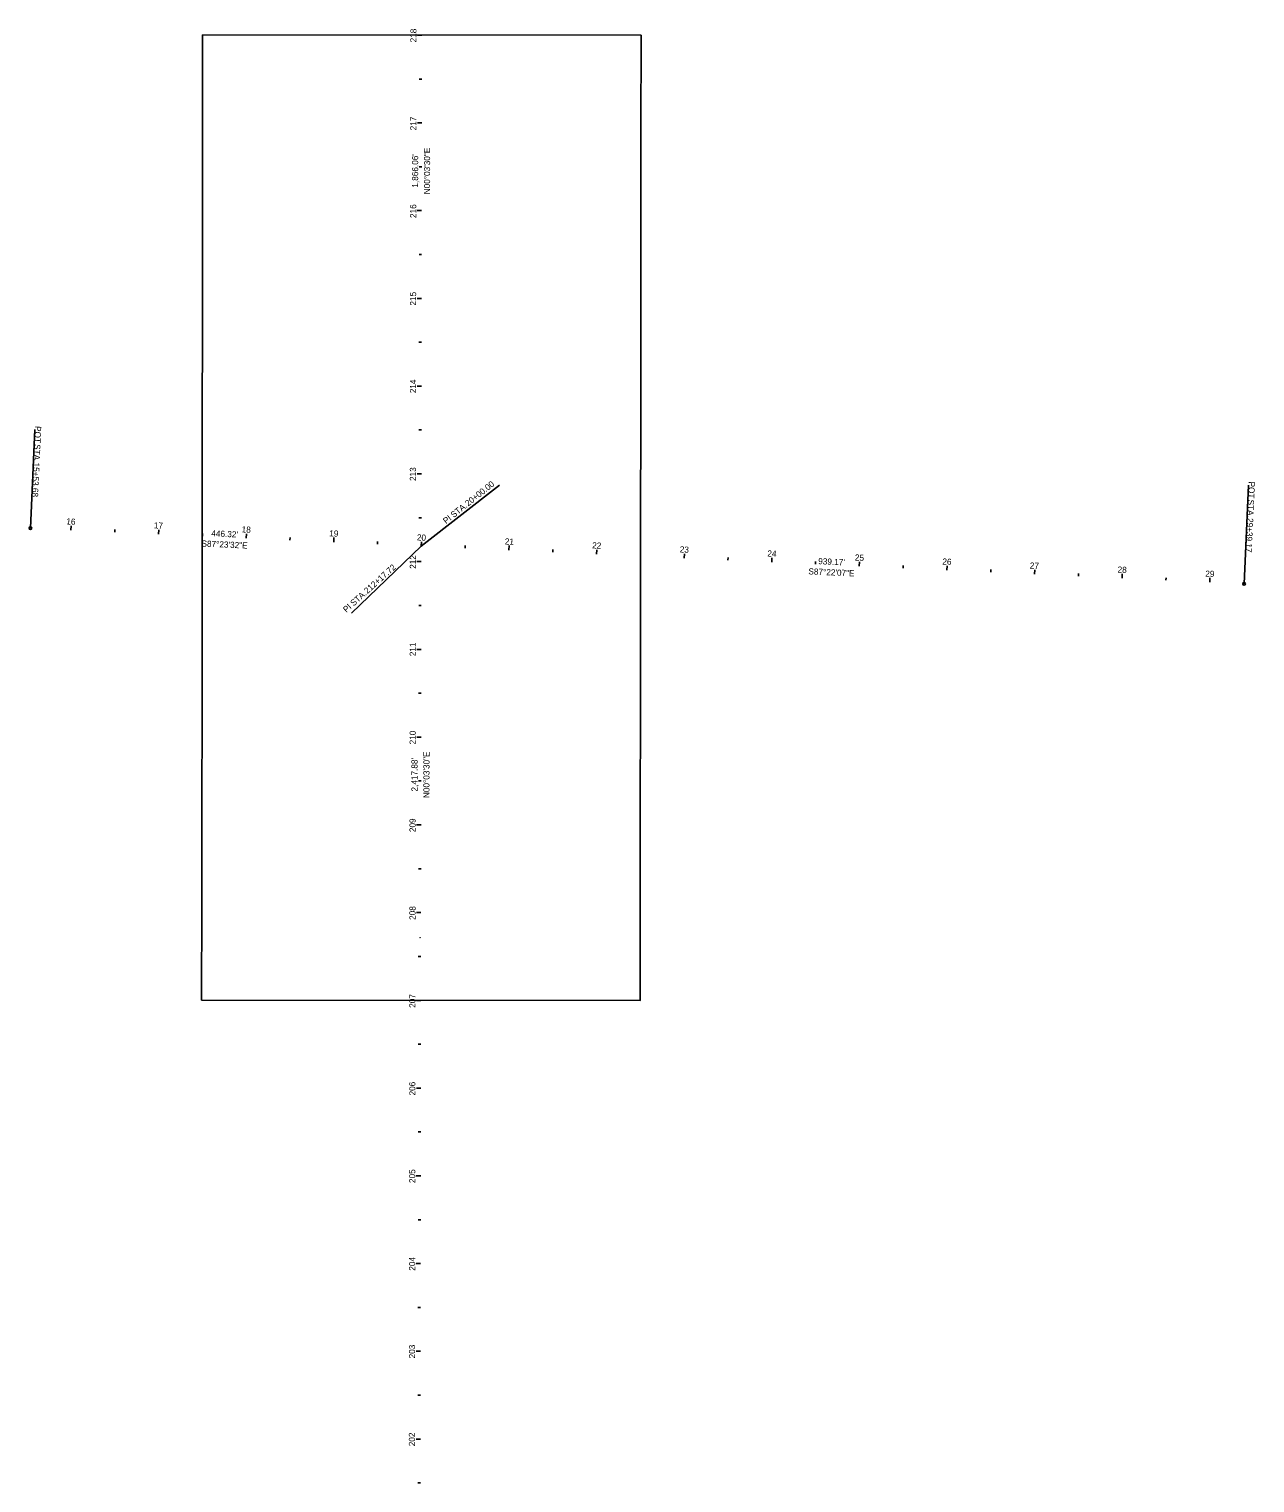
# Model space of a CAD drawing. Extents: x 1805326 to 1810276, y 297762 to 303660.
# Drawn here: x 1808220 to 1809618, y 300719 to 302376 of the extents above; entities that cross this region are included whole.
import ezdxf

# ---------------------------------------------------------------- set-up
doc = ezdxf.new("R2010")
doc.units = 0
for name, color, linetype in [('_CIVIL_CONSTRUCTION', 7, 'Continuous'), ('GE_P_Alignment_100_Bearings', 7, 'Continuous'), ('GE_P_Alignment_100_Cardinal_Points', 7, 'Continuous'), ('GE_P_Alignment_100_Distances', 7, 'Continuous'), ('GE_P_Alignment_100_Stations', 7, 'Continuous'), ('SH_Data', 7, 'Continuous'), ('SH_Named_Boundary', 7, 'Continuous')]:
    doc.layers.add(name, color=color, linetype=linetype)

msp = doc.modelspace()

# ---------------------------------------------------------------- linework, layer by layer
at = {"layer": '_CIVIL_CONSTRUCTION'}
msp.add_circle((1808666.1, 301340.6), 0.05, dxfattribs=at)
at = {"layer": 'GE_P_Alignment_100_Cardinal_Points'}
for p, q in [((1808221.7, 301807.3), (1808226.8, 301919.6)), ((1809605.7, 301743.8), (1809610.9, 301856.2))]:
    msp.add_line(p, q, dxfattribs=at)
for centre in [(1808221.7, 301807.3), (1809605.7, 301743.8)]:
    msp.add_circle(centre, 1.5, dxfattribs=at)
at = {"layer": 'GE_P_Alignment_100_Stations'}
for p, q in [((1808668.1, 302369.2), (1808663.1, 302369.2)), ((1808668.1, 302319.2), (1808665.1, 302319.2)), ((1808668, 302269.2), (1808663, 302269.2)), ((1808668, 302219.2), (1808665, 302219.2)), ((1808667.9, 302169.2), (1808662.9, 302169.2)), ((1808667.9, 302119.2), (1808664.9, 302119.2)), ((1808667.8, 302069.2), (1808662.8, 302069.2)), ((1808667.8, 302019.2), (1808664.8, 302019.2)), ((1808667.7, 301969.2), (1808662.7, 301969.2)), ((1808667.7, 301919.2), (1808664.7, 301919.2)), ((1808667.6, 301869.2), (1808662.6, 301869.2)), ((1808667.6, 301819.2), (1808664.6, 301819.2)), ((1808268, 301805.1), (1808268.2, 301810.1)), ((1808317.9, 301802.9), (1808318, 301805.9)), ((1808367.9, 301800.6), (1808368.1, 301805.6)), ((1808417.8, 301798.3), (1808417.9, 301801.3)), ((1808467.7, 301796), (1808468, 301801)), ((1808517.7, 301793.8), (1808517.8, 301796.8)), ((1808567.6, 301791.5), (1808567.9, 301796.5)), ((1808617.6, 301789.2), (1808617.7, 301792.2)), ((1808667.5, 301786.9), (1808667.8, 301791.9)), ((1808717.5, 301784.7), (1808717.6, 301787.7)), ((1808767.4, 301782.4), (1808767.7, 301787.4)), ((1808667.5, 301769.2), (1808662.5, 301769.2)), ((1808817.4, 301780.1), (1808817.5, 301783.1)), ((1808867.3, 301777.8), (1808867.6, 301782.8)), ((1808917.3, 301775.5), (1808917.4, 301778.5)), ((1808967.2, 301773.2), (1808967.5, 301778.2)), ((1809017.2, 301770.9), (1809017.3, 301773.9)), ((1809067.1, 301768.6), (1809067.4, 301773.6)), ((1809117.1, 301766.3), (1809117.2, 301769.3)), ((1809167, 301764), (1809167.2, 301769)), ((1809217, 301761.7), (1809217.1, 301764.7)), ((1809266.9, 301759.4), (1809267.1, 301764.4)), ((1809316.9, 301757.1), (1809317, 301760.1)), ((1809366.8, 301754.8), (1809367, 301759.8)), ((1809416.8, 301752.5), (1809416.9, 301755.5)), ((1809466.7, 301750.2), (1809466.9, 301755.2)), ((1809516.6, 301747.9), (1809516.8, 301750.9)), ((1809566.6, 301745.6), (1809566.8, 301750.6)), ((1808667.5, 301719.2), (1808664.5, 301719.2)), ((1808667.4, 301669.2), (1808662.4, 301669.2)), ((1808667.4, 301619.2), (1808664.4, 301619.2)), ((1808667.3, 301569.2), (1808662.3, 301569.2)), ((1808667.3, 301519.2), (1808664.3, 301519.2)), ((1808667.2, 301469.2), (1808662.2, 301469.2)), ((1808667.2, 301419.2), (1808664.2, 301419.2)), ((1808667.1, 301369.2), (1808662.1, 301369.2)), ((1808667.1, 301319.2), (1808664.1, 301319.2)), ((1808667, 301269.2), (1808662, 301269.2)), ((1808667, 301219.2), (1808664, 301219.2)), ((1808666.9, 301169.2), (1808661.9, 301169.2)), ((1808666.9, 301119.2), (1808663.9, 301119.2)), ((1808666.8, 301069.2), (1808661.8, 301069.2)), ((1808666.8, 301019.2), (1808663.8, 301019.2)), ((1808666.7, 300969.2), (1808661.7, 300969.2)), ((1808666.7, 300919.2), (1808663.7, 300919.2)), ((1808666.6, 300869.2), (1808661.6, 300869.2)), ((1808666.6, 300819.2), (1808663.6, 300819.2)), ((1808666.5, 300769.2), (1808661.5, 300769.2)), ((1808666.5, 300719.2), (1808663.5, 300719.2))]:
    msp.add_line(p, q, dxfattribs=at)
at = {"layer": 'SH_Data'}
for q in [(1808756.8, 301856.5), (1808587.8, 301710.6)]:
    msp.add_line((1808667.5, 301786.9), q, dxfattribs=at)
at = {"layer": 'SH_Named_Boundary'}
msp.add_lwpolyline([(1808417, 301269.5), (1808917, 301269), (1808917.1, 301379), (1808917.2, 301489), (1808917.4, 301599), (1808917.5, 301709), (1808917.6, 301819), (1808917.7, 301929), (1808917.8, 302039), (1808917.9, 302149), (1808918, 302259), (1808918.1, 302369), (1808418.1, 302369.5), (1808418, 302259.5), (1808417.9, 302149.5), (1808417.8, 302039.5), (1808417.7, 301929.5), (1808417.6, 301819.5), (1808417.5, 301709.5), (1808417.4, 301599.5), (1808417.2, 301489.5), (1808417.1, 301379.5)], close=True, dxfattribs=at)

# ---------------------------------------------------------------- texts
at = {"layer": 'GE_P_Alignment_100_Bearings'}
for s, rotation, p in [('N00°03\'30"E', 89.9418, (1808677.5, 302187.8)), ('S87°23\'32"E', 357.3922, (1808416.7, 301786.4)), ('S87°22\'07"E', 357.3686, (1809108.8, 301754.7)), ('N00°03\'30"E', 89.9418, (1808676.8, 301499.7))]:
    msp.add_text(s, height=7, rotation=rotation, dxfattribs=at).set_placement(p)
at = {"layer": 'GE_P_Alignment_100_Cardinal_Points'}
for s, rotation, p in [('POT', 267.3922, (1808227.1, 301923.8)), (' STA. ', 267.3922, (1808226.3, 301905.8)), ('15+53.68', 267.3922, (1808225.2, 301882.2)), ('20+00.00', 38.5061, (1808720.8, 301831.8)), ('POT', 267.3686, (1809611.2, 301860.6)), (' STA. ', 267.3686, (1809610.4, 301842.6)), ('PI', 38.5061, (1808695.7, 301811.8)), (' STA. ', 38.5061, (1808702.3, 301817.1)), ('29+39.17', 267.3686, (1809609.3, 301819)), ('212+17.72', 41.7874, (1808606, 301732.1)), ('PI', 41.7874, (1808582, 301710.7)), (' STA. ', 41.7874, (1808588.4, 301716.3))]:
    msp.add_text(s, height=7, rotation=rotation, dxfattribs=at).set_placement(p)
at = {"layer": 'GE_P_Alignment_100_Distances'}
for s, rotation, p in [("1,866.06'", 89.9418, (1808663.9, 302195.4)), ("446.32'", 357.3922, (1808427.9, 301798)), ("939.17'", 357.3686, (1809120, 301766.3)), ("2,417.88'", 89.9418, (1808663.2, 301507.2))]:
    msp.add_text(s, height=7, rotation=rotation, dxfattribs=at).set_placement(p)
at = {"layer": 'GE_P_Alignment_100_Stations'}
for s, rotation, p in [('218', 89.9418, (1808661.9, 302360.9)), ('217', 89.9418, (1808661.8, 302260.7)), ('216', 89.9418, (1808661.7, 302160.8)), ('215', 89.9418, (1808661.6, 302061)), ('214', 89.9418, (1808661.5, 301961.1)), ('213', 89.9418, (1808661.4, 301861.1)), ('16', 357.3922, (1808262.6, 301811.6)), ('17', 357.3922, (1808362.4, 301807.1)), ('18', 357.3922, (1808462.5, 301802.5)), ('19', 357.3922, (1808562.4, 301798)), ('20', 357.3922, (1808662.3, 301793.4)), ('21', 357.3686, (1808762.6, 301788.8)), ('22', 357.3686, (1808862.2, 301784.3)), ('23', 357.3686, (1808962.1, 301779.7)), ('212', 89.9418, (1808661.3, 301761)), ('24', 357.3686, (1809062, 301775.1)), ('25', 357.3686, (1809161.8, 301770.5)), ('26', 357.3686, (1809261.6, 301765.9)), ('27', 357.3686, (1809361.3, 301761.3)), ('28', 357.3686, (1809461.4, 301756.7)), ('29', 357.3686, (1809561.4, 301752.1)), ('211', 89.9418, (1808661.2, 301661.4)), ('210', 89.9418, (1808661.1, 301560.9)), ('209', 89.9418, (1808661, 301460.9)), ('208', 89.9418, (1808660.9, 301360.9)), ('207', 89.9418, (1808660.8, 301260.7)), ('206', 89.9418, (1808660.7, 301160.8)), ('205', 89.9418, (1808660.6, 301061)), ('204', 89.9418, (1808660.5, 300961.1)), ('203', 89.9418, (1808660.4, 300861.1)), ('202', 89.9418, (1808660.3, 300761))]:
    msp.add_text(s, height=7, rotation=rotation, dxfattribs=at).set_placement(p)

doc.saveas('drawing.dxf')
